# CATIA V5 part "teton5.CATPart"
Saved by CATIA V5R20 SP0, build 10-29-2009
Part number: teton5
Bounding box of the stored display mesh (mm): x 0 to 10, y -5.804 to 6.196, z -6.289 to 5.711
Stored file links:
  C:\Users\thinkmotion1\Desktop\IAO OK\IAO_2010_1458_splanchena\Correction_Khaled\teton5.CATPart
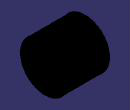
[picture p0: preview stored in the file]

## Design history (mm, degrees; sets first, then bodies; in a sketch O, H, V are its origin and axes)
Body1 (main body)
  Sketch1 on yz-plane, origin (0, 0, 0), H (0, 1, 0), V (0, 0, 1)
    circle A1 centre (0.1962, -0.2889) radius 6
    radius A1 = 6
  Pad1: profile Sketch1, direction (1, 0, 0), length 10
